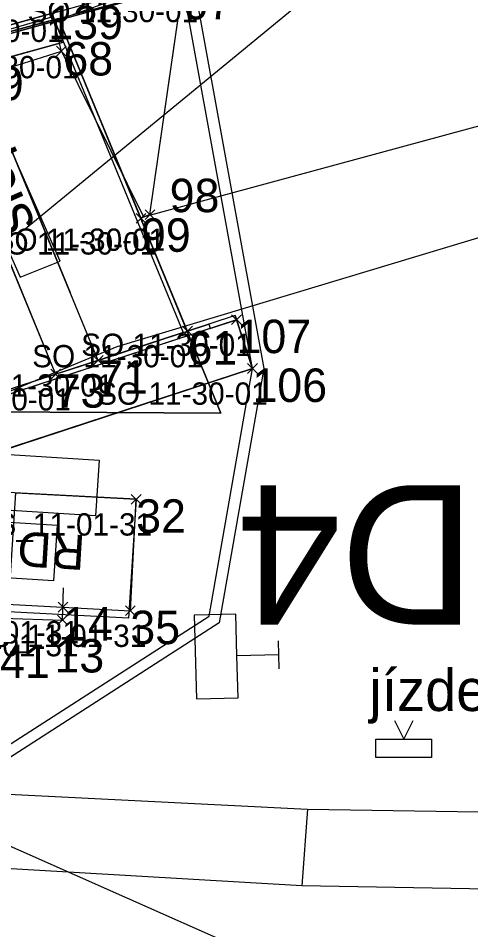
# Model space of a CAD drawing. Extents: x -728800 to -728100, y -1073200 to -1072700.
# Drawn here: x -728492.02 to -728483.9, y -1073043.64 to -1073027.3 of the extents above; entities that cross this region are included whole.
import ezdxf

# ---------------------------------------------------------------- set-up
doc = ezdxf.new("R2010")
doc.units = 0
for name, color, linetype in [('_NOR-návrh tenká', 7, 'Continuous'), ('_NOR-šraf_+-0', 7, 'Continuous'), ('_NOR-šraf_+6', 7, 'Continuous'), ('_NOR-šraf_bezbariéra', 7, 'Continuous'), ('_NOR-šraf_chodník', 7, 'Continuous'), ('_NOR-šraf_signální pás', 7, 'Continuous'), ('_NOR-šraf_varovný pás', 7, 'Continuous'), ('_NOR-šraf_vozovka', 7, 'Continuous'), ('_NOR-šraf_zeleň', 7, 'Continuous'), ('A1_OBVOD Spravy železnic', 7, 'Continuous'), ('A2_OBVOD STAVBY', 7, 'Continuous'), ('B1_body_poloha', 7, 'Continuous'), ('B2_body_číslo', 7, 'Continuous'), ('B3_body_popiska', 7, 'Continuous'), ('B6_JŽM', 7, 'Continuous'), ('KOS_kabelová trasa', 7, 'Continuous'), ('KOS_nové prvky PZZ', 7, 'Continuous'), ('KTA_PZZ rušené', 7, 'Continuous'), ('KTA_členění PS a SO', 7, 'Continuous'), ('ZA_01_Trvalý_pro_SŽDC_dle_UMVZST', 7, 'Continuous'), ('ZA_02_Dočasný_do_1_roku', 7, 'Continuous'), ('ZZZ_popisky', 7, 'Continuous')]:
    doc.layers.add(name, color=color, linetype=linetype)

msp = doc.modelspace()

# ---------------------------------------------------------------- linework, layer by layer
at = {"layer": '_NOR-návrh tenká'}
for p, q in [((-728489.66, -1073030.819), (-728489.068, -1073026.719)), ((-728490.424, -1073027.015), (-728491.368, -1073027.353)), ((-728491.368, -1073027.353), (-728491.408, -1073027.208)), ((-728491.368, -1073027.353), (-728489.062, -1073032.933)), ((-728492.771, -1073028.155), (-728491.091, -1073032.219)), ((-728489.66, -1073030.819), (-728489.821, -1073030.886)), ((-728488.131, -1073032.628), (-728487.82, -1073033.579))]:
    msp.add_line(p, q, dxfattribs=at)
for points in [[(-728489.108, -1073026.574), (-728492.964, -1073027.637)], [(-728489.068, -1073026.719), (-728492.924, -1073027.782)], [(-728488.985, -1073032.908), (-728491.29, -1073027.331)], [(-728491.214, -1073027.725), (-728492.818, -1073028.168)], [(-728488.131, -1073032.628), (-728488.985, -1073032.908)], [(-728488.106, -1073032.704), (-728496.63, -1073035.493)], [(-728489.062, -1073032.933), (-728496.655, -1073035.417)], [(-728487.82, -1073033.579), (-728495.393, -1073036.056)]]:
    msp.add_lwpolyline(points, dxfattribs=at)
at = {"layer": '_NOR-šraf_+-0'}
for points in [[(-728488.985, -1073032.908), (-728491.29, -1073027.331), (-728491.368, -1073027.353), (-728491.214, -1073027.725), (-728489.062, -1073032.933), (-728488.985, -1073032.908)], [(-728488.581, -1073032.86), (-728488.106, -1073032.704), (-728488.131, -1073032.628), (-728488.606, -1073032.784), (-728488.581, -1073032.86)]]:
    msp.add_lwpolyline(points, dxfattribs=at)
at = {"layer": '_NOR-šraf_+6'}
msp.add_lwpolyline([(-728496.655, -1073035.417), (-728491.352, -1073033.682), (-728490.59, -1073033.433), (-728489.062, -1073032.933), (-728488.985, -1073032.908), (-728488.606, -1073032.784), (-728488.594, -1073032.822), (-728488.581, -1073032.86), (-728496.554, -1073035.468), (-728496.63, -1073035.493), (-728496.655, -1073035.417), (-728496.655, -1073035.417)], dxfattribs=at)
at = {"layer": '_NOR-šraf_bezbariéra'}
msp.add_lwpolyline([(-728492.924, -1073027.782), (-728491.368, -1073027.353), (-728491.408, -1073027.208), (-728492.964, -1073027.637)], dxfattribs=at)
at = {"layer": '_NOR-šraf_chodník'}
for p, q in [((-728493.539, -1073028.392), (-728491.352, -1073033.682)), ((-728491.352, -1073033.682), (-728496.655, -1073035.417))]:
    msp.add_line(p, q, dxfattribs=at)
msp.add_lwpolyline([(-728490.59, -1073033.433), (-728492.771, -1073028.155), (-728491.214, -1073027.725), (-728489.062, -1073032.933), (-728490.59, -1073033.433)], dxfattribs=at)
at = {"layer": '_NOR-šraf_signální pás'}
for points in [[(-728490.59, -1073033.433), (-728492.771, -1073028.155), (-728492.818, -1073028.168)], [(-728493.539, -1073028.392), (-728491.352, -1073033.682), (-728490.59, -1073033.433), (-728490.59, -1073033.433)]]:
    msp.add_lwpolyline(points, dxfattribs=at)
at = {"layer": '_NOR-šraf_varovný pás'}
msp.add_lwpolyline([(-728492.818, -1073028.168), (-728492.771, -1073028.155), (-728491.214, -1073027.725), (-728491.368, -1073027.353), (-728492.924, -1073027.782)], dxfattribs=at)
at = {"layer": '_NOR-šraf_vozovka'}
msp.add_line((-728492.964, -1073027.637), (-728491.408, -1073027.208), dxfattribs=at)
at = {"layer": '_NOR-šraf_zeleň'}
for p, q in [((-728488.106, -1073032.704), (-728496.554, -1073035.468)), ((-728487.82, -1073033.579), (-728488.106, -1073032.704)), ((-728495.393, -1073036.056), (-728487.82, -1073033.579))]:
    msp.add_line(p, q, dxfattribs=at)
msp.add_lwpolyline([(-728489.821, -1073030.886), (-728489.66, -1073030.819), (-728489.068, -1073026.719), (-728490.404, -1073027.087), (-728491.29, -1073027.331), (-728489.821, -1073030.886), (-728489.821, -1073030.886)], dxfattribs=at)
at = {"layer": 'A1_OBVOD Spravy železnic'}
msp.add_lwpolyline([(-728503.24, -1073052.34), (-728501.946, -1073043.293), (-728501.19, -1073037.94), (-728499.78, -1073032.61), (-728497.54, -1073030.15), (-728493.68, -1073027.94), (-728443.97, -1073014.59), (-728443.68, -1073014.51), (-728441.09, -1073023.23), (-728428.92, -1073019.94), (-728429.82, -1073016.43), (-728427.49, -1073015.84), (-728421.24, -1073014.23), (-728422.34, -1073010.27), (-728422.77, -1073008.34), (-728418.21, -1073007), (-728380.57, -1072997.2), (-728343.1, -1072987.57), (-728330.49, -1072984.52), (-728326.79, -1072988.95)], dxfattribs=at)
at = {"layer": 'A2_OBVOD STAVBY'}
msp.add_lwpolyline([(-728488.873, -1073026.674), (-728487.617, -1073033.578), (-728488.418, -1073038.141), (-728493.164, -1073041.187), (-728493.918, -1073046.515)], dxfattribs=at)
at = {"layer": 'B1_body_poloha'}
for p, q in [((-728491.338, -1073027.8), (-728491.162, -1073027.976)), ((-728491.338, -1073027.976), (-728491.162, -1073027.8)), ((-728489.748, -1073030.731), (-728489.572, -1073030.907)), ((-728489.748, -1073030.907), (-728489.572, -1073030.731)), ((-728489.909, -1073030.798), (-728489.733, -1073030.974)), ((-728489.909, -1073030.974), (-728489.733, -1073030.798)), ((-728488.194, -1073032.616), (-728488.018, -1073032.792)), ((-728488.194, -1073032.792), (-728488.018, -1073032.616)), ((-728489.073, -1073032.82), (-728488.897, -1073032.996)), ((-728489.073, -1073032.996), (-728488.897, -1073032.82)), ((-728490.678, -1073033.344), (-728490.501, -1073033.521)), ((-728490.678, -1073033.521), (-728490.501, -1073033.344)), ((-728487.908, -1073033.491), (-728487.732, -1073033.667)), ((-728487.908, -1073033.667), (-728487.732, -1073033.491)), ((-728491.44, -1073033.594), (-728491.264, -1073033.77)), ((-728491.44, -1073033.77), (-728491.264, -1073033.594)), ((-728489.995, -1073035.837), (-728489.819, -1073036.013)), ((-728489.995, -1073036.013), (-728489.819, -1073035.837)), ((-728491.309, -1073037.77), (-728491.133, -1073037.946)), ((-728491.309, -1073037.946), (-728491.133, -1073037.77)), ((-728490.1, -1073037.834), (-728489.924, -1073038.01)), ((-728490.1, -1073038.01), (-728489.924, -1073037.834)), ((-728491.317, -1073038.002), (-728491.141, -1073038.178)), ((-728491.317, -1073038.178), (-728491.141, -1073038.002))]:
    msp.add_line(p, q, dxfattribs=at)
at = {"layer": 'B2_body_číslo'}
for p, q in [((-728491.214, -1073027.725), (-728491.214, -1073027.725)), ((-728489.821, -1073030.886), (-728489.821, -1073030.886)), ((-728489.66, -1073030.819), (-728489.66, -1073030.819)), ((-728488.106, -1073032.704), (-728488.106, -1073032.704)), ((-728488.985, -1073032.908), (-728488.985, -1073032.908)), ((-728490.59, -1073033.433), (-728490.59, -1073033.433)), ((-728487.82, -1073033.579), (-728487.82, -1073033.579)), ((-728491.352, -1073033.682), (-728491.352, -1073033.682)), ((-728489.907, -1073035.925), (-728489.907, -1073035.925)), ((-728491.221, -1073037.858), (-728491.221, -1073037.858)), ((-728490.012, -1073037.922), (-728490.012, -1073037.922)), ((-728491.229, -1073038.09), (-728491.229, -1073038.09))]:
    msp.add_line(p, q, dxfattribs=at)
at = {"layer": 'B6_JŽM'}
for p, q in [((-728487.341, -1073038.963), (-728487.355, -1073038.463)), ((-728485.605, -1073040.227), (-728485.602, -1073040.223))]:
    msp.add_line(p, q, dxfattribs=at)
for points in [[(-728491.25, -1073027.888), (-728489.777, -1073030.86), (-728476.655, -1073027.306), (-728450.209, -1073019.139)], [(-728498.56, -1073020.107), (-728494.628, -1073019.466), (-728491.401, -1073027.273), (-728495.275, -1073028.394), (-728498.56, -1073020.107)], [(-728449.745, -1073020.446), (-728480.35, -1073030.208), (-728490.255, -1073033.191), (-728496.482, -1073035.776)], [(-728495.275, -1073028.394), (-728495.063, -1073029.004), (-728493.479, -1073028.573), (-728491.99, -1073031.943), (-728491.271, -1073031.657), (-728492.733, -1073028.355), (-728491.25, -1073027.888), (-728491.401, -1073027.273)], [(-728496.482, -1073035.776), (-728497.494, -1073036.644), (-728498.316, -1073037.996), (-728498.528, -1073038.603), (-728498.459, -1073039.486), (-728498.149, -1073040.128), (-728497.533, -1073040.603), (-728496.825, -1073040.892), (-728494.827, -1073041.079), (-728486.835, -1073041.479), (-728486.937, -1073042.858), (-728494.923, -1073042.391), (-728498.977, -1073042.014), (-728499.069, -1073042.727), (-728513.553, -1073040.642)], [(-728487.348, -1073038.713), (-728488.098, -1073038.733), (-728488.118, -1073037.983), (-728488.867, -1073038.003), (-728488.827, -1073039.503), (-728488.078, -1073039.483), (-728488.098, -1073038.733)], [(-728485.272, -1073039.89), (-728485.105, -1073040.223), (-728484.938, -1073039.89)], [(-728486.835, -1073041.479), (-728474.913, -1073041.665), (-728461.988, -1073041.13), (-728461.886, -1073042.523), (-728474.902, -1073043.068), (-728486.937, -1073042.858)]]:
    msp.add_lwpolyline(points, dxfattribs=at)
msp.add_lwpolyline([(-728485.605, -1073040.223), (-728484.605, -1073040.223), (-728484.605, -1073040.557), (-728485.605, -1073040.557)], close=True, dxfattribs=at)
at = {"layer": 'KOS_kabelová trasa'}
msp.add_lwpolyline([(-728495.185, -1073037.974), (-728493.377, -1073038.021), (-728491.229, -1073038.09), (-728491.21, -1073037.515)], dxfattribs=at)
at = {"layer": 'KOS_nové prvky PZZ'}
msp.add_lwpolyline([(-728489.907, -1073035.925), (-728492.903, -1073035.767), (-728493.008, -1073037.764), (-728490.012, -1073037.922)], close=True, dxfattribs=at)
at = {"layer": 'KTA_PZZ rušené'}
for points in [[(-728490.571, -1073035.223), (-728490.635, -1073036.221), (-728492.631, -1073036.093), (-728492.567, -1073035.095), (-728490.571, -1073035.223)], [(-728490.044, -1073038.056), (-728492.203, -1073037.942), (-728492.066, -1073035.811), (-728489.907, -1073035.925), (-728490.044, -1073038.056)], [(-728491.324, -1073036.39), (-728491.388, -1073037.388), (-728493.384, -1073037.26), (-728493.32, -1073036.262), (-728491.324, -1073036.39)]]:
    msp.add_lwpolyline(points, dxfattribs=at)
at = {"layer": 'KTA_členění PS a SO'}
msp.add_line((-728484.574, -1073025.064), (-728491.931, -1073031.102), dxfattribs=at)
at = {"layer": 'ZA_01_Trvalý_pro_SŽDC_dle_UMVZST'}
msp.add_lwpolyline([(-728500.719, -1073036.161), (-728501.19, -1073037.94), (-728493.84, -1073039.37), (-728493.51, -1073034.35), (-728488.39, -1073034.38), (-728491.302, -1073027.301), (-728493.68, -1073027.94), (-728497.54, -1073030.15), (-728499.78, -1073032.61)], close=True, dxfattribs=at)
at = {"layer": 'ZA_02_Dočasný_do_1_roku'}
for points in [[(-728494.117, -1073046.49), (-728493.349, -1073041.068), (-728488.6, -1073038.02), (-728487.82, -1073033.579), (-728489.068, -1073026.719)], [(-728493.127, -1073026.851), (-728494.629, -1073027.35), (-728496.284, -1073028.164), (-728498.455, -1073029.806), (-728499.694, -1073031.116), (-728500.79, -1073032.701), (-728501.615, -1073034.32), (-728501.802, -1073034.888), (-728501.559, -1073036.1), (-728500.719, -1073036.161), (-728499.78, -1073032.61), (-728497.54, -1073030.15), (-728493.68, -1073027.94), (-728491.302, -1073027.301), (-728488.39, -1073034.38), (-728493.51, -1073034.35), (-728493.84, -1073039.37), (-728501.19, -1073037.94), (-728502.042, -1073043.972)]]:
    msp.add_lwpolyline(points, dxfattribs=at)
at = {"layer": 'ZZZ_popisky'}
msp.add_lwpolyline([(-728495.863, -1073040.505), (-728482.3, -1073046.517), (-728480.971, -1073043.517)], dxfattribs=at)

# ---------------------------------------------------------------- texts
at = {"layer": 'B2_body_číslo'}
for s, p in [('67', (-728489.068, -1073027.319)), ('139', (-728491.483, -1073027.674)), ('68', (-728491.214, -1073028.325)), ('69', (-728492.818, -1073028.768)), ('98', (-728489.306, -1073030.776)), ('99', (-728489.821, -1073031.486)), ('107', (-728488.106, -1073033.304)), ('61', (-728488.985, -1073033.508)), ('71', (-728490.59, -1073034.033)), ('106', (-728487.82, -1073034.179)), ('73', (-728491.352, -1073034.282)), ('32', (-728489.907, -1073036.525)), ('14', (-728491.221, -1073038.458)), ('35', (-728490.012, -1073038.522)), ('41', (-728492.351, -1073039.13)), ('13', (-728491.374, -1073039.03))]:
    msp.add_text(s, height=0.6, dxfattribs=at).set_placement(p)
at = {"layer": 'B3_body_popiska'}
for s, p in [('SO 11-30-01', (-728491.857, -1073027.369)), ('SO 11-30-01', (-728494.272, -1073027.724)), ('SO 11-30-01', (-728494.003, -1073028.375)), ('SO 11-30-01', (-728492.61, -1073031.536)), ('SO 11-30-01', (-728492.449, -1073031.469)), ('SO 11-30-01', (-728490.895, -1073033.354)), ('SO 11-30-01', (-728491.774, -1073033.558)), ('SO 11-30-01', (-728493.379, -1073034.083)), ('SO 11-30-01', (-728490.609, -1073034.229)), ('SO 11-30-01', (-728494.141, -1073034.332)), ('PS_11-01-31', (-728492.772, -1073036.575)), ('PS_11-01-31', (-728494.086, -1073038.508)), ('PS_11-01-31', (-728492.877, -1073038.572)), ('PS_11-01-31', (-728494.094, -1073038.74))]:
    msp.add_text(s, height=0.4, dxfattribs=at).set_placement(p)
at = {"layer": 'B6_JŽM'}
msp.add_text('slepecká dl ', height=0.75, rotation=113.8819, dxfattribs=at).set_placement((-728491.704, -1073031.002))
msp.add_text('jízdenky stojan', height=0.75, dxfattribs=at).set_placement((-728485.725, -1073039.721))
at = {"layer": 'KOS_nové prvky PZZ'}
msp.add_text('RD', height=0.625, rotation=176.5903, dxfattribs=at).set_placement((-728490.809, -1073036.57))
at = {"layer": 'ZA_02_Dočasný_do_1_roku'}
msp.add_text('D4', height=2.5, rotation=180, dxfattribs=at).set_placement((-728483.821, -1073035.672))

doc.saveas('drawing.dxf')
